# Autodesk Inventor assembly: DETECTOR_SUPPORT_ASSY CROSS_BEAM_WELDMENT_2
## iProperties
Shininess: 64.0
Length Units: 11272
Angle Units: 11279
Time Units: 11290
Mass Units: 11286
Length Display Precision: 3
Angle Display Precision: 2
Compacted: True
Part Number: DETECTOR_SUPPORT_ASSY CROSS_BEAM_WELDMENT_2
Document SubType Name: Assembly
Created: 2004-08
Designer: John Blackburn
Manufacturer: Standard
Standards Organization: Custom
Density: 0.0
Volumn: 0.0
Area: 0.0
PropertySet Name: Model Information
Control State: 0
Master: False
Checked Out: False
Author: John Blackburn
